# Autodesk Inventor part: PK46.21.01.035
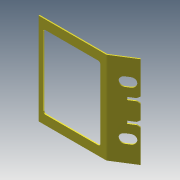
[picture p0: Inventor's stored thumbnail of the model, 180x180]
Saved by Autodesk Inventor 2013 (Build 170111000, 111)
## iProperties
Created: 2005-04
Part Number: PK46.21.01.035
Material: Steel, Mild
Document SubType Name: Обычные детали
Designer: salex
Manufacturer: Standard
Standards Organization: Custom
Density: 7.86 g/cm^3
Sheet Metal Rule: Default
Author: salex
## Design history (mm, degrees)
node "ФлнОтгиб1"
sketch "Эскиз2"
  geometry: L1 (0, 800)-(0, 0) reference; L2 (-206.772, 800)-(0, 800) reference; L3 (-60, 655)-(-100, 655); L4 (-100, 575)-(-60, 575); L5 (-85, 478)-(0, 478); L6 (0, 478)-(0, 502); L7 (0, 502)-(-85, 502); L8 (-85, 502)-(-85, 478); L9 (0, 400)-(-88.452, 400); L10 (-85, 322)-(0, 322); L11 (0, 322)-(0, 298); L12 (-85, 298)-(-85, 322); L13 (-100, 225)-(-60, 225); L14 (0, 298)-(-85, 298); L15 (-60, 145)-(-100, 145); A1 r 40 centre (-100, 615) between (-100, 655) and (-100, 575); A2 r 40 centre (-60, 615) between (-60, 575) and (-60, 655); A3 r 40 centre (-100, 185) between (-100, 225) and (-100, 145); A4 r 40 centre (-60, 185) between (-60, 145) and (-60, 225)
  constraints: 26 end point, 10 symmetric about line, 8 point on circle, 4 centre point, 4 parallel, 4 tangent, 2 perpendicular, 1 horizontal, 1 midpoint, 1 point on line, 2 other
  dimensions: "d10" = 298 distance between parallel lines of L7 L2; "d11" = 24 distance between parallel lines of L7 L5; "d12" = 85 distance between parallel lines of L1 L8; "d13" = 145 distance between parallel lines of L2 L3; "d14" = 40 distance of A2.centre A1.centre; "d15" = 40 radius of A1; "d16" = 60 distance from line of A2.centre L1
extrude "Выдавливание1" cut sketch "Эскиз2" stored distance "d17" = 10; taper "d18" = 0 deg
feature "Угловая фаска1" dims "d19" = 15, "d20" = 25, angle "d21" = 45 deg
sketch "Эскиз3"
  geometry: L1 (0, 800)-(584.242, 800) reference; L2 (0, 800)-(0, 0) reference; L3 (0, 0)-(584.242, 0) reference; L4 (40, 720)-(540, 720); L5 (540, 720)-(540, 80); L6 (540, 80)-(40, 80); L7 (584.242, 0)-(584.242, 800) reference; L8 (40, 720)-(40, 80)
  constraints: 8 end point, 4 parallel, 1 perpendicular
  dimensions: "d23" = 80 distance between parallel lines of L4 L1; "d24" = 540 distance between parallel lines of L5 L2; "d34" = 40 distance between parallel lines of L8 L2; "d35" = 640 distance of L4.start L6.end
extrude "Выдавливание2" cut sketch "Эскиз3" stored distance "d26" = 10; taper "d27" = 0 deg
fillet "Сопряжение1" dims "d33" = 20
fillet "Сопряжение2" dims "d36" = 20
chamfer "Фаска1" distance "d37" = 25 (= d20); stored, may be unused: second distance "d38" = 15 (= d19), angle "d39" = 45 deg
chamfer "Фаска2" distance "d40" = 25 (= d20); stored, may be unused: second distance "d41" = 15 (= d19), angle "d42" = 45 deg
chamfer "Фаска3" distance "d43" = 25 (= d20); stored, may be unused: second distance "d44" = 15 (= d19), angle "d45" = 45 deg
body "Solid1"
sketch "Эскиз1"
  geometry: L1 (0, 0)-(590, 0); L2 (590, 0)-(770, 113)
  constraints: 4 end point, 1 horizontal, 1 other
  dimensions: "d0" = 590 distance of L1.start L1.end; "d1" = 113 distance from line of L2.end L1; "d2" = 770 horizontal distance of L1.start L2.end
feature "Плакирование1" dims "d3" = 800, "d4" = 10 (= BendReliefWidth), "d6" = 20 (= MinimumRemnant), "d8" = 20 (= BendRadius), "d9" = 10, "Thickness" = 10
feature "Изгиб1" dims "d4" = 10 (= BendReliefWidth), "d5" = 5 (= BendReliefDepth), "d6" = 20 (= MinimumRemnant), "d7" = 20 (= BendRadius), "d8" = 20 (= BendRadius), "d9" = 10, "SeamGap" = 0.01, "Thickness" = 10
other parameters: "BendRadius" = 20, "BendReliefDepth" = 5 (= 0.5 x Thickness)
